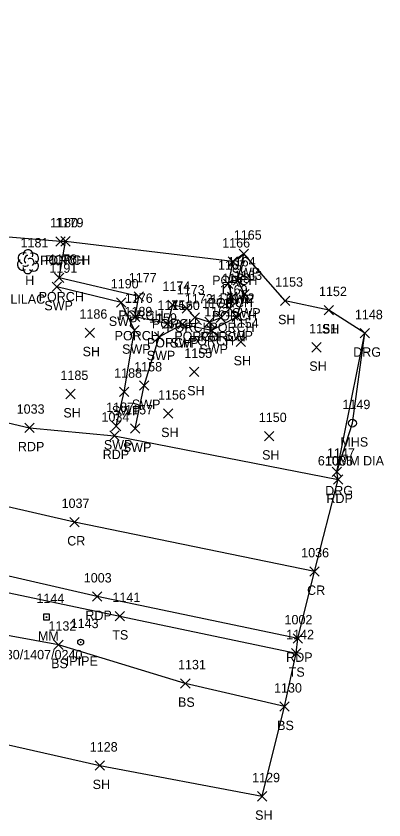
# Model space of a CAD drawing. Extents: x 1616726 to 1619875, y 273782 to 276557.
# Drawn here: x 1617283.4 to 1617362, y 276063.5 to 276234.9 of the extents above; entities that cross this region are included whole.
import ezdxf

# ---------------------------------------------------------------- set-up
doc = ezdxf.new("R2010")
doc.units = 0
for name, color, linetype in [('L_A', 7, 'Continuous'), ('L_C', 7, 'Continuous'), ('L_I', 7, 'Continuous'), ('L_TIC', 7, 'Continuous'), ('LBF', 7, 'Continuous'), ('LELB', 7, 'Continuous'), ('LSOGP', 7, 'Continuous'), ('LTD', 7, 'Continuous'), ('M_A', 7, 'Continuous'), ('M_I', 7, 'Continuous'), ('MPIP', 7, 'Continuous'), ('P_A', 7, 'Continuous'), ('P_I', 7, 'Continuous'), ('P_TIC', 7, 'Continuous'), ('PET', 7, 'Continuous'), ('PRC', 7, 'Continuous'), ('R_A', 7, 'Continuous'), ('R_I', 7, 'Continuous'), ('R_TIC', 7, 'Continuous'), ('RDG', 7, 'Continuous'), ('RSW', 7, 'Continuous'), ('S_A', 7, 'Continuous'), ('S_C', 7, 'Continuous'), ('S_I', 7, 'Continuous'), ('SRM', 7, 'Continuous'), ('U_A', 7, 'Continuous'), ('U_C', 7, 'Continuous'), ('U_I', 7, 'Continuous'), ('USMH', 7, 'Continuous')]:
    doc.layers.add(name, color=color, linetype=linetype)

msp = doc.modelspace()

# ---------------------------------------------------------------- linework, layer by layer
at = {"layer": 'L_TIC'}
for points in [[(1617291.93, 276185.82), (1617293.93, 276187.82)], [(1617293.93, 276185.82), (1617291.93, 276187.82)], [(1617293.01, 276185.84), (1617295.01, 276187.84)], [(1617295.01, 276185.84), (1617293.01, 276187.84)], [(1617328.68, 276181.52), (1617330.68, 276183.52)], [(1617330.68, 276181.52), (1617328.68, 276183.52)], [(1617291.63, 276178.05), (1617293.63, 276180.05)], [(1617293.63, 276178.05), (1617291.63, 276180.05)], [(1617327.71, 276176.78), (1617329.71, 276178.78)], [(1617329.71, 276176.78), (1617327.71, 276178.78)], [(1617308.64, 276174.1), (1617310.64, 276176.1)], [(1617310.64, 276174.1), (1617308.64, 276176.1)], [(1617328.6, 276173.98), (1617330.6, 276175.98)], [(1617330.6, 276173.98), (1617328.6, 276175.98)], [(1617339.88, 276173.18), (1617341.88, 276175.18)], [(1617341.88, 276173.18), (1617339.88, 276175.18)], [(1617315.81, 276172.28), (1617317.81, 276174.28)], [(1617317.81, 276172.28), (1617315.81, 276174.28)], [(1617318.89, 276171.53), (1617320.89, 276173.53)], [(1617320.89, 276171.53), (1617318.89, 276173.53)], [(1617328.09, 276171.51), (1617330.09, 276173.51)], [(1617330.09, 276171.51), (1617328.09, 276173.51)], [(1617349.23, 276171.16), (1617351.23, 276173.16)], [(1617351.23, 276171.16), (1617349.23, 276173.16)], [(1617307.84, 276169.73), (1617309.84, 276171.73)], [(1617309.84, 276169.73), (1617307.84, 276171.73)], [(1617320.6, 276169.59), (1617322.6, 276171.59)], [(1617322.6, 276169.59), (1617320.6, 276171.59)], [(1617326.16, 276169.52), (1617328.16, 276171.52)], [(1617328.16, 276169.52), (1617326.16, 276171.52)], [(1617314.73, 276168.23), (1617316.73, 276170.23)], [(1617316.73, 276168.23), (1617314.73, 276170.23)], [(1617323.7, 276168.64), (1617325.7, 276170.64)], [(1617325.7, 276168.64), (1617323.7, 276170.64)], [(1617298.15, 276166.35), (1617300.15, 276168.35)], [(1617300.15, 276166.35), (1617298.15, 276168.35)], [(1617330.39, 276164.41), (1617332.39, 276166.41)], [(1617332.39, 276164.41), (1617330.39, 276166.41)], [(1617346.55, 276163.24), (1617348.55, 276165.24)], [(1617348.55, 276163.24), (1617346.55, 276165.24)], [(1617320.48, 276158), (1617322.48, 276160)], [(1617322.48, 276158), (1617320.48, 276160)], [(1617294.04, 276153.29), (1617296.04, 276155.29)], [(1617296.04, 276153.29), (1617294.04, 276155.29)], [(1617314.92, 276149.11), (1617316.92, 276151.11)], [(1617316.92, 276149.11), (1617314.92, 276151.11)], [(1617336.47, 276144.31), (1617338.47, 276146.31)], [(1617338.47, 276144.31), (1617336.47, 276146.31)], [(1617304.57, 276105.94), (1617306.57, 276107.94)], [(1617306.57, 276105.94), (1617304.57, 276107.94)], [(1617291.48, 276099.84), (1617293.48, 276101.84)], [(1617293.48, 276099.84), (1617291.48, 276101.84)], [(1617342.23, 276098.02), (1617344.23, 276100.02)], [(1617344.23, 276098.02), (1617342.23, 276100.02)], [(1617318.57, 276091.6), (1617320.57, 276093.6)], [(1617320.57, 276091.6), (1617318.57, 276093.6)], [(1617339.73, 276086.64), (1617341.73, 276088.64)], [(1617341.73, 276086.64), (1617339.73, 276088.64)], [(1617300.29, 276074.07), (1617302.29, 276076.07)], [(1617302.29, 276074.07), (1617300.29, 276076.07)], [(1617334.98, 276067.52), (1617336.98, 276069.52)], [(1617336.98, 276067.52), (1617334.98, 276069.52)]]:
    msp.add_lwpolyline(points, dxfattribs=at)
at = {"layer": 'LBF'}
msp.add_lwpolyline([(1617329.68, 276182.52), (1617328.71, 276177.78), (1617329.6, 276174.98), (1617329.09, 276172.51), (1617327.16, 276170.52), (1617324.7, 276169.64), (1617321.6, 276170.59), (1617319.89, 276172.53), (1617316.81, 276173.28), (1617315.73, 276169.23), (1617308.84, 276170.73), (1617309.64, 276175.1), (1617292.63, 276179.05), (1617294.01, 276186.84), (1617292.93, 276186.82)], dxfattribs=at)
at = {"layer": 'LELB'}
for points in [[(1617218.87, 276122.21), (1617238.22, 276119.71), (1617256.33, 276115.96), (1617273.77, 276113.62), (1617305.57, 276106.94), (1617343.23, 276099.02)], [(1617340.73, 276087.64), (1617319.57, 276092.6), (1617292.48, 276100.84), (1617267.13, 276105.43), (1617247.7, 276108.57), (1617231.05, 276112.5), (1617219.7, 276108.1)]]:
    msp.add_lwpolyline(points, dxfattribs=at)
at = {"layer": 'LSOGP'}
msp.add_lwpolyline([(1617277.3, 276080.47), (1617301.29, 276075.07), (1617335.98, 276068.52), (1617340.73, 276087.64), (1617343.23, 276099.02), (1617343.6, 276102.19), (1617347.13, 276116.47), (1617352.2, 276136.04), (1617351.94, 276137.7), (1617355.25, 276148.07), (1617357.91, 276167.24), (1617350.23, 276172.16), (1617340.88, 276174.18), (1617332.09, 276184.2), (1617329.68, 276182.52), (1617294.01, 276186.84), (1617292.93, 276186.82), (1617269.79, 276188.72)], dxfattribs=at)
at = {"layer": 'LTD'}
msp.add_line((1617285.95, 276182.55), (1617285.95, 276182.55), dxfattribs=at)
msp.add_line((1617285.95, 276182.55), (1617285.95, 276182.55), dxfattribs=at)
msp.add_arc((1617286, 276183.99), 1.05, 335.5272, 180.9563, dxfattribs=at)
for centre, major_axis, ratio, start_param, end_param in [((1617285.16, 276183.22), (1.21, -0.51), 0.895232, 1.570796, 4.712389), ((1617285.74, 276183.01), (-0.208, -0.792), 0.645439, 3.141593, 6.283185), ((1617286.45, 276182.39), (-0.5, 0.667), 0.989748, 3.141593, 6.283185), ((1617286.99, 276183.14), (-1.14, -0.48), 0.949671, 1.570796, 4.712389), ((1617284.87, 276181.85), (0.58, -1.04), 0.959034, 3.141593, 6.283185), ((1617285.49, 276181.8), (-0.625, -0.083), 0.423636, 0, 3.141593), ((1617286.95, 276181.72), (-1.09, 0.79), 0.841452, 1.570796, 4.712389), ((1617285.95, 276181.05), (0.26, 1.06), 0.942809, 1.570796, 4.712389)]:
    msp.add_ellipse(centre, major_axis=major_axis, ratio=ratio, start_param=start_param, end_param=end_param, dxfattribs=at)
at = {"layer": 'MPIP'}
for radius in [0.625, 0.0833]:
    msp.add_circle((1617297.22, 276101.38), radius, dxfattribs=at)
at = {"layer": 'P_TIC'}
for points in [[(1617285.33, 276146.09), (1617287.33, 276148.09)], [(1617287.33, 276146.09), (1617285.33, 276148.09)], [(1617303.44, 276144.41), (1617305.44, 276146.41)], [(1617305.44, 276144.41), (1617303.44, 276146.41)], [(1617351.2, 276135.04), (1617353.2, 276137.04)], [(1617353.2, 276135.04), (1617351.2, 276137.04)], [(1617294.92, 276126), (1617296.92, 276128)], [(1617296.92, 276126), (1617294.92, 276128)], [(1617346.13, 276115.47), (1617348.13, 276117.47)], [(1617348.13, 276115.47), (1617346.13, 276117.47)], [(1617299.74, 276110.11), (1617301.74, 276112.11)], [(1617301.74, 276110.11), (1617299.74, 276112.11)], [(1617342.6, 276101.19), (1617344.6, 276103.19)], [(1617344.6, 276101.19), (1617342.6, 276103.19)]]:
    msp.add_lwpolyline(points, dxfattribs=at)
at = {"layer": 'PET'}
for points in [[(1616989.43, 276201.18), (1617018.47, 276198.31), (1617030.26, 276200.68), (1617036.67, 276206.24), (1617039.51, 276213.46), (1617039.81, 276219.44), (1617036.61, 276227.11), (1617032.44, 276230.39), (1617046.65, 276234.32), (1617061.09, 276238.88), (1617067.9, 276234.23), (1617072.4, 276230.99), (1617088.6, 276220.19), (1617112.48, 276205), (1617131.16, 276194.64), (1617156.36, 276182.31), (1617186.3, 276169.87), (1617215.5, 276159.97), (1617247.44, 276151.44), (1617259.73, 276148.35), (1617264.1, 276152.29), (1617286.33, 276147.09), (1617304.44, 276145.41), (1617352.2, 276136.04)], [(1617343.6, 276102.19), (1617300.74, 276111.11), (1617263.27, 276119.69), (1617236.26, 276126.17), (1617212.86, 276130.65), (1617190.89, 276138.89), (1617148.81, 276155.79), (1617124.37, 276159.73), (1617097.21, 276164.33), (1617058.67, 276171.51)]]:
    msp.add_lwpolyline(points, dxfattribs=at)
at = {"layer": 'PRC'}
msp.add_lwpolyline([(1617347.13, 276116.47), (1617295.92, 276127), (1617256.55, 276135.98), (1617216.87, 276146.76), (1617173.09, 276161.72), (1617139.46, 276175.96), (1617104.94, 276194.23), (1617079.38, 276210.71), (1617058.93, 276224.92), (1617047.07, 276234.03)], dxfattribs=at)
at = {"layer": 'R_TIC'}
for points in [[(1617331.09, 276183.2), (1617333.09, 276185.2)], [(1617333.09, 276183.2), (1617331.09, 276185.2)], [(1617291.11, 276176.14), (1617293.11, 276178.14)], [(1617293.11, 276176.14), (1617291.11, 276178.14)], [(1617329.79, 276177.49), (1617331.79, 276179.49)], [(1617331.79, 276177.49), (1617329.79, 276179.49)], [(1617331.19, 276174.6), (1617333.19, 276176.6)], [(1617333.19, 276174.6), (1617331.19, 276176.6)], [(1617304.86, 276172.81), (1617306.86, 276174.81)], [(1617306.86, 276172.81), (1617304.86, 276174.81)], [(1617329.55, 276169.75), (1617331.55, 276171.75)], [(1617331.55, 276169.75), (1617329.55, 276171.75)], [(1617317.97, 276168.2), (1617319.97, 276170.2)], [(1617319.97, 276168.2), (1617317.97, 276170.2)], [(1617307.71, 276166.87), (1617309.71, 276168.87)], [(1617309.71, 276166.87), (1617307.71, 276168.87)], [(1617324.21, 276166.87), (1617326.21, 276168.87)], [(1617326.21, 276166.87), (1617324.21, 276168.87)], [(1617356.91, 276166.24), (1617358.91, 276168.24)], [(1617358.91, 276166.24), (1617356.91, 276168.24)], [(1617312.96, 276165.51), (1617314.96, 276167.51)], [(1617314.96, 276165.51), (1617312.96, 276167.51)], [(1617305.51, 276153.76), (1617307.51, 276155.76)], [(1617307.51, 276153.76), (1617305.51, 276155.76)], [(1617309.78, 276155.11), (1617311.78, 276157.11)], [(1617311.78, 276155.11), (1617309.78, 276157.11)], [(1617303.81, 276146.47), (1617305.81, 276148.47)], [(1617305.81, 276146.47), (1617303.81, 276148.47)], [(1617307.87, 276145.94), (1617309.87, 276147.94)], [(1617309.87, 276145.94), (1617307.87, 276147.94)], [(1617350.94, 276136.7), (1617352.94, 276138.7)], [(1617352.94, 276136.7), (1617350.94, 276138.7)]]:
    msp.add_lwpolyline(points, dxfattribs=at)
at = {"layer": 'RDG'}
msp.add_lwpolyline([(1617351.94, 276137.7), (1617357.91, 276167.24)], dxfattribs=at)
at = {"layer": 'RSW'}
for points in [[(1617308.87, 276146.94), (1617310.78, 276156.11), (1617313.96, 276166.51), (1617318.97, 276169.2), (1617325.21, 276167.87), (1617330.55, 276170.75), (1617332.19, 276175.6), (1617330.79, 276178.49), (1617332.09, 276184.2)], [(1617304.81, 276147.47), (1617306.51, 276154.76), (1617308.71, 276167.87), (1617305.86, 276173.81), (1617292.11, 276177.14)]]:
    msp.add_lwpolyline(points, dxfattribs=at)
at = {"layer": 'SRM'}
for p, q in [((1617290.57, 276107.39), (1617289.32, 276107.39)), ((1617289.32, 276107.39), (1617289.32, 276106.14)), ((1617290.57, 276107.39), (1617289.32, 276107.39)), ((1617289.32, 276107.39), (1617289.32, 276106.14)), ((1617289.32, 276106.14), (1617290.57, 276106.14)), ((1617289.32, 276106.14), (1617290.57, 276106.14)), ((1617290.57, 276106.14), (1617290.57, 276107.39)), ((1617290.57, 276106.14), (1617290.57, 276107.39))]:
    msp.add_line(p, q, dxfattribs=at)
msp.add_circle((1617289.92, 276106.73), 0.0833, dxfattribs=at)
at = {"layer": 'USMH'}
for p, q in [((1617355.25, 276148.07), (1617355.25, 276148.07)), ((1617356.09, 276148.07), (1617356.09, 276148.07))]:
    msp.add_line(p, q, dxfattribs=at)
msp.add_circle((1617355.25, 276148.07), 0.833, dxfattribs=at)

# ---------------------------------------------------------------- texts
at = {"layer": 'L_A'}
for s, p in [('PORCH', (1617288.55, 276181.82)), ('PORCH', (1617289.63, 276181.84)), ('H', (1617285.38, 276177.55)), ('PORCH', (1617325.3, 276177.52)), ('PORCH', (1617288.25, 276174.05)), ('PORCH', (1617324.33, 276172.78)), ('PORCH', (1617305.26, 276170.1)), ('PORCH', (1617325.23, 276169.98)), ('SH', (1617339.37, 276169.18)), ('PORCH', (1617312.43, 276168.28)), ('PORCH', (1617315.51, 276167.53)), ('PORCH', (1617324.71, 276167.51)), ('PORCH', (1617304.47, 276165.73)), ('SH', (1617348.72, 276167.16)), ('PORCH', (1617311.36, 276164.23)), ('PORCH', (1617317.22, 276165.59)), ('PORCH', (1617320.32, 276164.64)), ('PORCH', (1617322.78, 276165.52)), ('SH', (1617297.64, 276162.35)), ('SH', (1617329.88, 276160.41)), ('SH', (1617346.04, 276159.24)), ('SH', (1617319.97, 276154)), ('SH', (1617293.53, 276149.29)), ('SH', (1617314.41, 276145.11)), ('SH', (1617335.96, 276140.31)), ('TS', (1617303.97, 276101.94)), ('BS', (1617290.92, 276095.84)), ('TS', (1617341.64, 276094.02)), ('BS', (1617318.01, 276087.6)), ('BS', (1617339.17, 276082.64)), ('SH', (1617299.78, 276070.07)), ('SH', (1617334.47, 276063.52))]:
    msp.add_text(s, height=2, dxfattribs=at).set_placement(p)
at = {"layer": 'L_C'}
msp.add_text('LILAC', height=2, dxfattribs=at).set_placement((1617282.22, 276173.55))
at = {"layer": 'L_I'}
for s, p in [('1180', (1617290.71, 276189.82)), ('1179', (1617291.87, 276189.84)), ('1181', (1617284.39, 276185.55)), ('1166', (1617327.45, 276185.52)), ('1178', (1617290.51, 276182.05)), ('1167', (1617326.54, 276180.78)), ('1177', (1617307.51, 276178.1)), ('1168', (1617327.43, 276177.98)), ('1174', (1617314.68, 276176.28)), ('1153', (1617338.75, 276177.18)), ('1173', (1617317.76, 276175.53)), ('1169', (1617326.9, 276175.51)), ('1152', (1617348.11, 276175.16)), ('1176', (1617306.66, 276173.73)), ('1172', (1617319.47, 276173.59)), ('1171', (1617323.14, 276172.64)), ('1170', (1617324.95, 276173.52)), ('1175', (1617313.61, 276172.23)), ('1186', (1617296.97, 276170.35)), ('1154', (1617329.27, 276168.41)), ('1151', (1617345.99, 276167.24)), ('1155', (1617319.35, 276162)), ('1185', (1617292.91, 276157.29)), ('1156', (1617313.74, 276153.11)), ('1150', (1617335.26, 276148.31)), ('1141', (1617304.01, 276109.94)), ('1132', (1617290.35, 276103.84)), ('1142', (1617341.1, 276102.02)), ('1131', (1617318.01, 276095.6)), ('1130', (1617338.51, 276090.64)), ('1128', (1617299.17, 276078.07)), ('1129', (1617333.84, 276071.52))]:
    msp.add_text(s, height=2, dxfattribs=at).set_placement(p)
at = {"layer": 'M_A'}
msp.add_text('IPIPE', height=2, dxfattribs=at).set_placement((1617294.05, 276096.38))
at = {"layer": 'M_I'}
msp.add_text('1143', height=2, dxfattribs=at).set_placement((1617295.09, 276104.38))
at = {"layer": 'P_A'}
for s, p in [('RDP', (1617283.82, 276142.09)), ('RDP', (1617301.93, 276140.41)), ('RDP', (1617349.69, 276131.04)), ('CR', (1617294.35, 276122)), ('CR', (1617345.57, 276111.47)), ('RDP', (1617298.23, 276106.11)), ('RDP', (1617341.09, 276097.19))]:
    msp.add_text(s, height=2, dxfattribs=at).set_placement(p)
at = {"layer": 'P_I'}
for s, p in [('1033', (1617283.56, 276150.09)), ('1034', (1617301.67, 276148.41)), ('1035', (1617349.43, 276139.04)), ('1037', (1617293.15, 276130)), ('1036', (1617344.31, 276119.47)), ('1003', (1617297.89, 276114.11)), ('1002', (1617340.75, 276105.19))]:
    msp.add_text(s, height=2, dxfattribs=at).set_placement(p)
at = {"layer": 'R_A'}
for s, p in [('SWP', (1617329.45, 276179.2)), ('SWP', (1617328.15, 276173.49)), ('SWP', (1617289.47, 276172.14)), ('SWP', (1617329.55, 276170.6)), ('SWP', (1617303.23, 276168.81)), ('SWP', (1617327.91, 276165.75)), ('SWP', (1617316.33, 276164.2)), ('SWP', (1617306.07, 276162.87)), ('SWP', (1617322.57, 276162.87)), ('SWP', (1617311.32, 276161.51)), ('DRG', (1617355.4, 276162.24)), ('SWP', (1617308.15, 276151.11)), ('SWP', (1617303.87, 276149.76)), ('SWP', (1617302.17, 276142.47)), ('SWP', (1617306.23, 276141.94)), ('DRG', (1617349.43, 276132.7))]:
    msp.add_text(s, height=2, dxfattribs=at).set_placement(p)
at = {"layer": 'R_I'}
for s, p in [('1165', (1617329.92, 276187.2)), ('1164', (1617328.61, 276181.49)), ('1191', (1617290.55, 276180.14)), ('1163', (1617330.01, 276178.6)), ('1190', (1617303.65, 276176.81)), ('1162', (1617328.38, 276173.75)), ('1189', (1617306.58, 276170.87)), ('1160', (1617316.71, 276172.2)), ('1161', (1617323.61, 276170.87)), ('1159', (1617311.82, 276169.51)), ('1148', (1617355.78, 276170.24)), ('1158', (1617308.66, 276159.11)), ('1188', (1617304.38, 276157.76)), ('1187', (1617302.68, 276150.47)), ('1157', (1617306.74, 276149.94)), ('1147', (1617349.81, 276140.7))]:
    msp.add_text(s, height=2, dxfattribs=at).set_placement(p)
at = {"layer": 'S_A'}
msp.add_text('MM', height=2, dxfattribs=at).set_placement((1617288.11, 276101.73))
at = {"layer": 'S_C'}
msp.add_text('1030/1407/0240', height=2, dxfattribs=at).set_placement((1617278.26, 276097.73))
at = {"layer": 'S_I'}
msp.add_text('1144', height=2, dxfattribs=at).set_placement((1617287.79, 276109.73))
at = {"layer": 'U_A'}
msp.add_text('MHS', height=2, dxfattribs=at).set_placement((1617352.67, 276143.07))
at = {"layer": 'U_C'}
msp.add_text('610MM DIA', height=2, dxfattribs=at).set_placement((1617347.86, 276139.07))
at = {"layer": 'U_I'}
msp.add_text('1149', height=2, dxfattribs=at).set_placement((1617353.12, 276151.07))

doc.saveas('drawing.dxf')
